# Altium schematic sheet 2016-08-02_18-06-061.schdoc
size 313 x 127 mm; SheetNumber: 1; SheetTotal: 1
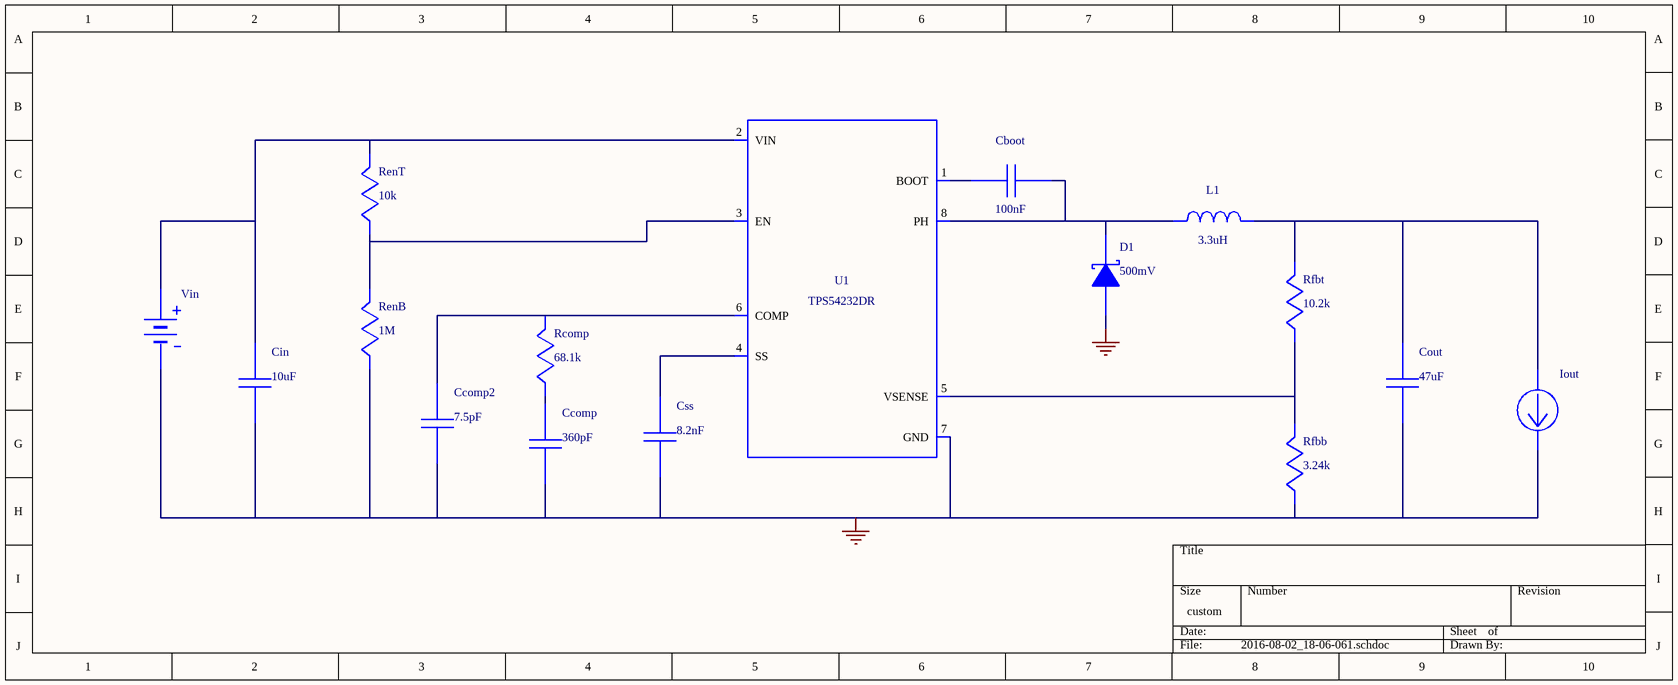
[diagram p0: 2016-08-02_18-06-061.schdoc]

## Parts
Cboot  value 100nF  (hidden comment: GRM155R61A104KA01D)
Ccomp  value 360pF  (hidden comment: GRM1555C1H361JA01D)
Ccomp2  value 7.5pF  (hidden comment: GRM1555C1H7R5CA01D)
Cin  value 10uF  (hidden comment: C1210C106K8PACTU)
Cout  value 47uF  (hidden comment: GRM31CC80J476KE18L)
Css  value 8.2nF  (hidden comment: GRM033R61A822KA01D)
D1  value 500mV  (hidden comment: B220-13-F)
Iout  WB_CURRENT_LOAD  (value not drawn)
L1  value 3.3uH  (hidden comment: SRN6045-3R3Y)
Rcomp  value 68.1k  (hidden comment: CRCW040268K1FKED)
RenB  value 1M  (hidden comment: CRCW04021M00FKED)
RenT  value 10k  (hidden comment: CRCW040210K0FKED)
Rfbb  value 3.24k  (hidden comment: CRCW04023K24FKED)
Rfbt  value 10.2k  (hidden comment: CRCW040210K2FKED)
U1  TPS54231DR  (value not drawn)
Vin  WB_BATTERY  (value not drawn)

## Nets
0: Ccomp.2 Ccomp2.2 Cin.2 Cout.2 Css.2 D1.2(A) Iout.2(-) RenB.2 Rfbb.2 U1.7(GND) Vin.2(-)
NetCboot_1: Cboot.1 U1.1(BOOT)
NetCboot_2: Cboot.2 D1.1(K) L1.2 U1.8(PH)
NetCcomp2_1: Ccomp2.1 Rcomp.1 U1.6(COMP)
NetCcomp_1: Ccomp.1 Rcomp.2
NetCin_1: Cin.1 RenT.1 U1.2(VIN) Vin.1(+)
NetCout_1: Cout.1 Iout.1(+) L1.1 Rfbt.1
NetCss_1: Css.1 U1.4(SS)
NetRenB_1: RenB.1 RenT.2 U1.3(EN)
NetRfbb_1: Rfbb.1 Rfbt.2 U1.5(VSENSE)

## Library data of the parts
Cboot = GRM155R61A104KA01D: GRM155R61A104KA0; Manufacturer Name: MuRata
Ccomp = GRM1555C1H361JA01D: GRM1555C1H361JA0; Manufacturer Name: MuRata
Ccomp2 = GRM1555C1H7R5CA01D: GRM1555C1H7R5CA0; Manufacturer Name: MuRata
Cin = C1210C106K8PACTU: Manufacturer Name: Kemet
Cout = GRM31CC80J476KE18L: GRM31CC80J476KE1; Manufacturer Name: MuRata
Css = GRM033R61A822KA01D: GRM033R61A822KA0; Manufacturer Name: MuRata
D1 = B220-13-F: Manufacturer Name: Diodes Inc.
L1 = SRN6045-3R3Y: Manufacturer Name: Bourns
Rcomp = CRCW040268K1FKED: Manufacturer Name: Vishay-Dale
RenB = CRCW04021M00FKED: Manufacturer Name: Vishay-Dale
RenT = CRCW040210K0FKED: Manufacturer Name: Vishay-Dale
Rfbb = CRCW04023K24FKED: Manufacturer Name: Vishay-Dale
Rfbt = CRCW040210K2FKED: Manufacturer Name: Vishay-Dale
U1 = TPS54231DR: TPS54232DR; Manufacturer Name: Texas Instruments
